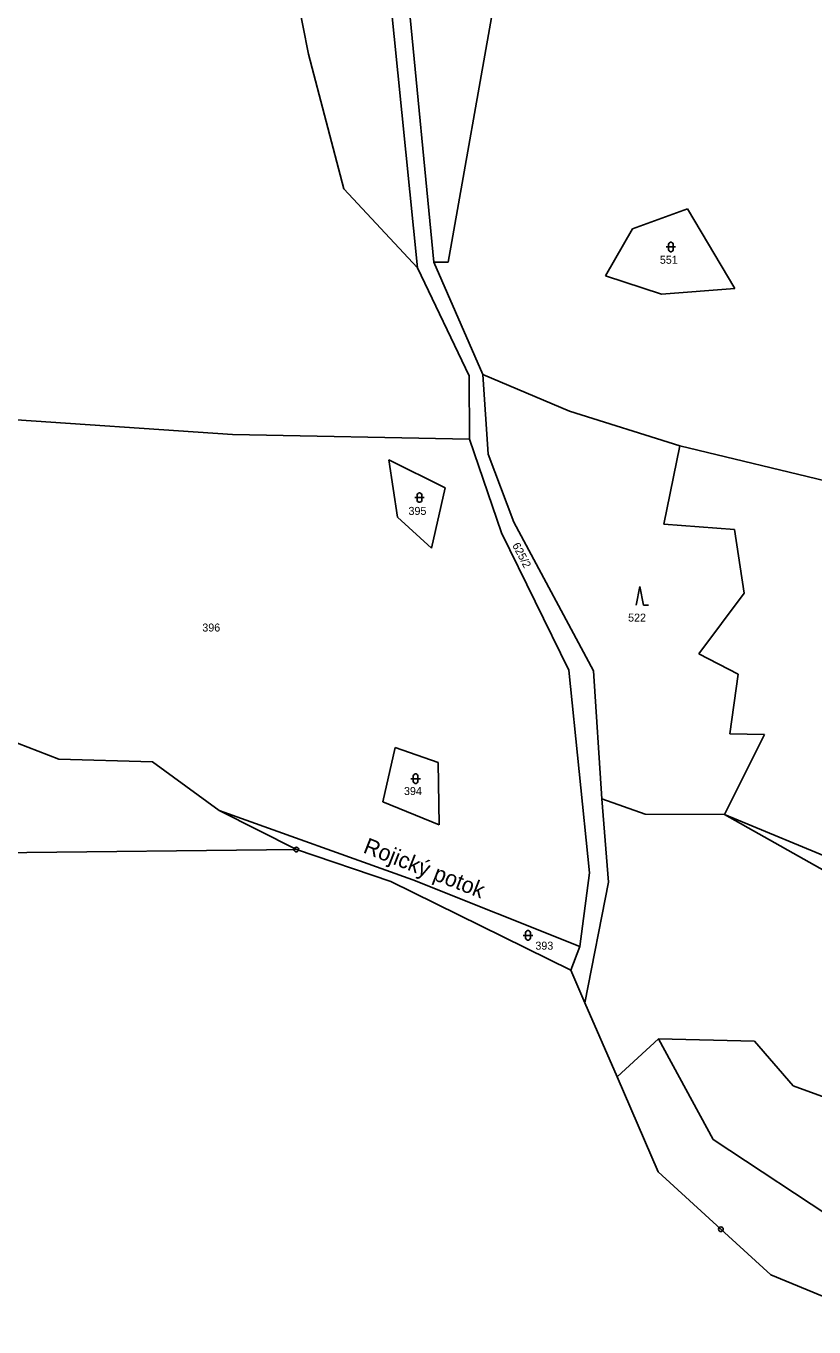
# Model space of a CAD drawing. Extents: x -794421 to -792735, y -1117671 to -1115559.
# Drawn here: x -793818.1 to -793650.8, y -1117521.2 to -1117244.8 of the extents above; entities that cross this region are included whole.
import ezdxf

# ---------------------------------------------------------------- set-up
doc = ezdxf.new("R2010")
doc.units = 0
for name, color, linetype in [('Vrstva 1', 7, 'Continuous'), ('Vrstva 14', 7, 'Continuous'), ('Vrstva 23', 7, 'Continuous'), ('Vrstva 28', 7, 'Continuous'), ('Vrstva 4', 7, 'Continuous'), ('Vrstva 43', 7, 'Continuous')]:
    doc.layers.add(name, color=color, linetype=linetype)

msp = doc.modelspace()

# ---------------------------------------------------------------- linework, layer by layer
at = {"layer": 'Vrstva 1'}
for p, q in [((-793745.22, -1117194.22), (-793734.99, -1117296.17)), ((-793731.46, -1117294.94), (-793740.7, -1117200.01)), ((-793758.11, -1117250.74), (-793767.43, -1117202.86)), ((-793718.45, -1117238.37), (-793728.42, -1117294.94)), ((-793750.63, -1117279.34), (-793758.11, -1117250.74)), ((-793734.99, -1117296.17), (-793750.63, -1117279.34)), ((-793689.28, -1117287.83), (-793677.6, -1117283.63)), ((-793677.6, -1117283.63), (-793667.56, -1117300.52)), ((-793695.03, -1117297.87), (-793689.28, -1117287.83)), ((-793734.99, -1117296.17), (-793723.98, -1117319.08)), ((-793721.12, -1117318.81), (-793731.46, -1117294.94)), ((-793731.46, -1117294.94), (-793728.42, -1117294.94)), ((-793683.17, -1117301.71), (-793695.03, -1117297.87)), ((-793667.56, -1117300.52), (-793683.17, -1117301.71)), ((-793723.98, -1117319.08), (-793723.9, -1117332.52)), ((-793721.12, -1117318.81), (-793702.66, -1117326.58)), ((-793719.93, -1117335.72), (-793721.12, -1117318.81)), ((-793851.54, -1117326.32), (-793774.25, -1117331.53)), ((-793702.66, -1117326.58), (-793679.29, -1117333.94)), ((-793774.25, -1117331.53), (-793723.9, -1117332.52)), ((-793723.9, -1117332.52), (-793717.14, -1117352.43)), ((-793714.52, -1117350.16), (-793719.93, -1117335.72)), ((-793679.29, -1117333.94), (-793682.63, -1117350.57)), ((-793679.29, -1117333.94), (-793646.35, -1117341.87)), ((-793741.02, -1117336.9), (-793729.06, -1117342.85)), ((-793739.2, -1117349.11), (-793741.02, -1117336.9)), ((-793729.06, -1117342.85), (-793731.99, -1117355.69)), ((-793731.99, -1117355.69), (-793739.2, -1117349.11)), ((-793717.14, -1117352.43), (-793702.85, -1117381.63)), ((-793697.58, -1117381.79), (-793714.52, -1117350.16)), ((-793682.63, -1117350.57), (-793667.63, -1117351.72)), ((-793667.63, -1117351.72), (-793665.61, -1117365.29)), ((-793665.61, -1117365.29), (-793675.21, -1117378.12)), ((-793675.21, -1117378.12), (-793666.88, -1117382.46)), ((-793702.85, -1117381.63), (-793698.41, -1117424.69)), ((-793695.82, -1117408.95), (-793697.58, -1117381.79)), ((-793666.88, -1117382.46), (-793668.63, -1117395.13)), ((-793825.44, -1117394.95), (-793811.12, -1117400.52)), ((-793661.27, -1117395.31), (-793669.75, -1117412.29)), ((-793668.63, -1117395.13), (-793661.27, -1117395.31)), ((-793742.34, -1117409.57), (-793739.67, -1117398.06)), ((-793739.67, -1117398.06), (-793730.58, -1117401.25)), ((-793811.12, -1117400.52), (-793791.22, -1117401.09)), ((-793791.22, -1117401.09), (-793777.05, -1117411.46)), ((-793730.58, -1117401.25), (-793730.37, -1117414.51)), ((-793730.37, -1117414.51), (-793742.34, -1117409.57)), ((-793686.59, -1117412.2), (-793695.82, -1117408.95)), ((-793695.82, -1117408.95), (-793694.38, -1117426.63)), ((-793777.05, -1117411.46), (-793760.68, -1117419.72)), ((-793777.05, -1117411.46), (-793735.95, -1117426.19)), ((-793669.75, -1117412.29), (-793686.59, -1117412.2)), ((-793669.75, -1117412.29), (-793635.79, -1117426.44)), ((-793640.97, -1117428.56), (-793669.75, -1117412.29)), ((-793735.95, -1117426.19), (-793700.5, -1117440.32)), ((-793698.41, -1117424.69), (-793700.5, -1117440.32)), ((-793694.38, -1117426.63), (-793699.41, -1117452.26)), ((-793700.5, -1117440.32), (-793702.41, -1117445.34)), ((-793683.78, -1117459.92), (-793692.58, -1117468.03)), ((-793683.78, -1117459.92), (-793663.39, -1117460.43)), ((-793672.21, -1117481.31), (-793683.78, -1117459.92)), ((-793663.39, -1117460.43), (-793655.22, -1117469.9)), ((-793655.22, -1117469.9), (-793635.22, -1117477.22)), ((-793641.21, -1117501.77), (-793672.21, -1117481.31))]:
    msp.add_line(p, q, dxfattribs=at)
at = {"layer": 'Vrstva 23'}
for p, q in [((-793681.66, -1117291.11), (-793681.56, -1117290.91)), ((-793681.66, -1117292.31), (-793681.66, -1117291.11)), ((-793681.56, -1117290.91), (-793681.46, -1117290.81)), ((-793681.46, -1117290.81), (-793681.26, -1117290.71)), ((-793681.26, -1117290.71), (-793681.06, -1117290.71)), ((-793681.06, -1117290.71), (-793680.86, -1117290.81)), ((-793680.86, -1117290.81), (-793680.76, -1117290.91)), ((-793680.76, -1117290.91), (-793680.66, -1117291.11)), ((-793680.66, -1117291.11), (-793680.66, -1117292.31)), ((-793682.16, -1117291.71), (-793680.16, -1117291.71)), ((-793681.56, -1117292.51), (-793681.66, -1117292.31)), ((-793681.46, -1117292.61), (-793681.56, -1117292.51)), ((-793681.26, -1117292.71), (-793681.46, -1117292.61)), ((-793681.06, -1117292.71), (-793681.26, -1117292.71)), ((-793680.86, -1117292.61), (-793681.06, -1117292.71)), ((-793680.76, -1117292.51), (-793680.86, -1117292.61)), ((-793680.66, -1117292.31), (-793680.76, -1117292.51)), ((-793735.04, -1117344.35), (-793734.94, -1117344.15)), ((-793734.94, -1117344.15), (-793734.84, -1117344.05)), ((-793734.84, -1117344.05), (-793734.64, -1117343.95)), ((-793734.64, -1117343.95), (-793734.44, -1117343.95)), ((-793734.44, -1117343.95), (-793734.24, -1117344.05)), ((-793734.24, -1117344.05), (-793734.14, -1117344.15)), ((-793734.14, -1117344.15), (-793734.04, -1117344.35)), ((-793735.54, -1117344.95), (-793733.54, -1117344.95)), ((-793735.04, -1117345.55), (-793735.04, -1117344.35)), ((-793734.94, -1117345.75), (-793735.04, -1117345.55)), ((-793734.84, -1117345.85), (-793734.94, -1117345.75)), ((-793734.64, -1117345.95), (-793734.84, -1117345.85)), ((-793734.44, -1117345.95), (-793734.64, -1117345.95)), ((-793734.24, -1117345.85), (-793734.44, -1117345.95)), ((-793734.14, -1117345.75), (-793734.24, -1117345.85)), ((-793734.04, -1117345.55), (-793734.14, -1117345.75)), ((-793734.04, -1117344.35), (-793734.04, -1117345.55)), ((-793688.54, -1117367.83), (-793687.74, -1117363.83)), ((-793687.74, -1117363.83), (-793686.94, -1117367.83)), ((-793686.94, -1117367.83), (-793685.94, -1117367.83)), ((-793736.35, -1117404.67), (-793734.35, -1117404.67)), ((-793735.85, -1117404.07), (-793735.75, -1117403.87)), ((-793735.85, -1117405.27), (-793735.85, -1117404.07)), ((-793735.75, -1117403.87), (-793735.65, -1117403.77)), ((-793735.65, -1117403.77), (-793735.45, -1117403.67)), ((-793735.45, -1117403.67), (-793735.25, -1117403.67)), ((-793735.25, -1117403.67), (-793735.05, -1117403.77)), ((-793735.05, -1117403.77), (-793734.95, -1117403.87)), ((-793734.95, -1117403.87), (-793734.85, -1117404.07)), ((-793734.85, -1117404.07), (-793734.85, -1117405.27)), ((-793735.75, -1117405.47), (-793735.85, -1117405.27)), ((-793735.65, -1117405.57), (-793735.75, -1117405.47)), ((-793735.45, -1117405.67), (-793735.65, -1117405.57)), ((-793735.25, -1117405.67), (-793735.45, -1117405.67)), ((-793735.05, -1117405.57), (-793735.25, -1117405.67)), ((-793734.95, -1117405.47), (-793735.05, -1117405.57)), ((-793734.85, -1117405.27), (-793734.95, -1117405.47)), ((-793712.5, -1117437.96), (-793710.5, -1117437.96)), ((-793712, -1117437.36), (-793711.9, -1117437.16)), ((-793712, -1117438.56), (-793712, -1117437.36)), ((-793711.9, -1117437.16), (-793711.8, -1117437.06)), ((-793711.8, -1117437.06), (-793711.6, -1117436.96)), ((-793711.6, -1117436.96), (-793711.4, -1117436.96)), ((-793711.4, -1117436.96), (-793711.2, -1117437.06)), ((-793711.2, -1117437.06), (-793711.1, -1117437.16)), ((-793711.1, -1117437.16), (-793711, -1117437.36)), ((-793711, -1117437.36), (-793711, -1117438.56)), ((-793711.9, -1117438.76), (-793712, -1117438.56)), ((-793711.8, -1117438.86), (-793711.9, -1117438.76)), ((-793711.6, -1117438.96), (-793711.8, -1117438.86)), ((-793711.4, -1117438.96), (-793711.6, -1117438.96)), ((-793711.2, -1117438.86), (-793711.4, -1117438.96)), ((-793711.1, -1117438.76), (-793711.2, -1117438.86)), ((-793711, -1117438.56), (-793711.1, -1117438.76))]:
    msp.add_line(p, q, dxfattribs=at)
at = {"layer": 'Vrstva 28'}
for centre, radius in [((-793760.68, -1117419.72), 0.5), ((-793760.68, -1117419.72), 0.01), ((-793670.54, -1117500.38), 0.5), ((-793670.54, -1117500.38), 0.01)]:
    msp.add_circle(centre, radius, dxfattribs=at)
at = {"layer": 'Vrstva 4'}
for p, q in [((-793839.08, -1117420.61), (-793760.68, -1117419.72)), ((-793760.68, -1117419.72), (-793740.64, -1117426.5)), ((-793740.64, -1117426.5), (-793702.41, -1117445.34)), ((-793702.41, -1117445.34), (-793699.41, -1117452.26)), ((-793699.41, -1117452.26), (-793692.58, -1117468.03)), ((-793692.58, -1117468.03), (-793683.83, -1117488.22)), ((-793683.83, -1117488.22), (-793670.54, -1117500.38)), ((-793670.54, -1117500.38), (-793659.95, -1117510.07)), ((-793659.95, -1117510.07), (-793633.17, -1117521.16))]:
    msp.add_line(p, q, dxfattribs=at)

# ---------------------------------------------------------------- texts
at = {"layer": 'Vrstva 14'}
for s, p in [('551', (-793683.503, -1117295.27)), ('395', (-793736.863, -1117348.63)), ('396', (-793780.637, -1117373.41)), ('522', (-793690.243, -1117371.3)), ('394', (-793737.823, -1117408.14)), ('393', (-793709.927, -1117441))]:
    msp.add_text(s, height=1.7, dxfattribs=at).set_placement(p)
msp.add_text('625/2', height=1.7, rotation=297.57771, dxfattribs=at).set_placement((-793714.893, -1117355.061))
at = {"layer": 'Vrstva 43'}
msp.add_text('Rojický potok', height=3.4, rotation=338.6511, dxfattribs=at).set_placement((-793746.69, -1117420.3))

doc.saveas('drawing.dxf')
